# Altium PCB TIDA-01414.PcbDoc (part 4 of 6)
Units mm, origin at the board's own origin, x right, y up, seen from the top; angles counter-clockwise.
Board outline 400 x 135 mm, 4 copper layers (Top Copper, Copper Layer 2, Copper Layer 3, Bottom Copper), stack 1.567 mm thick; 835 components, 519 nets, 2420 pads, 2045 vias.
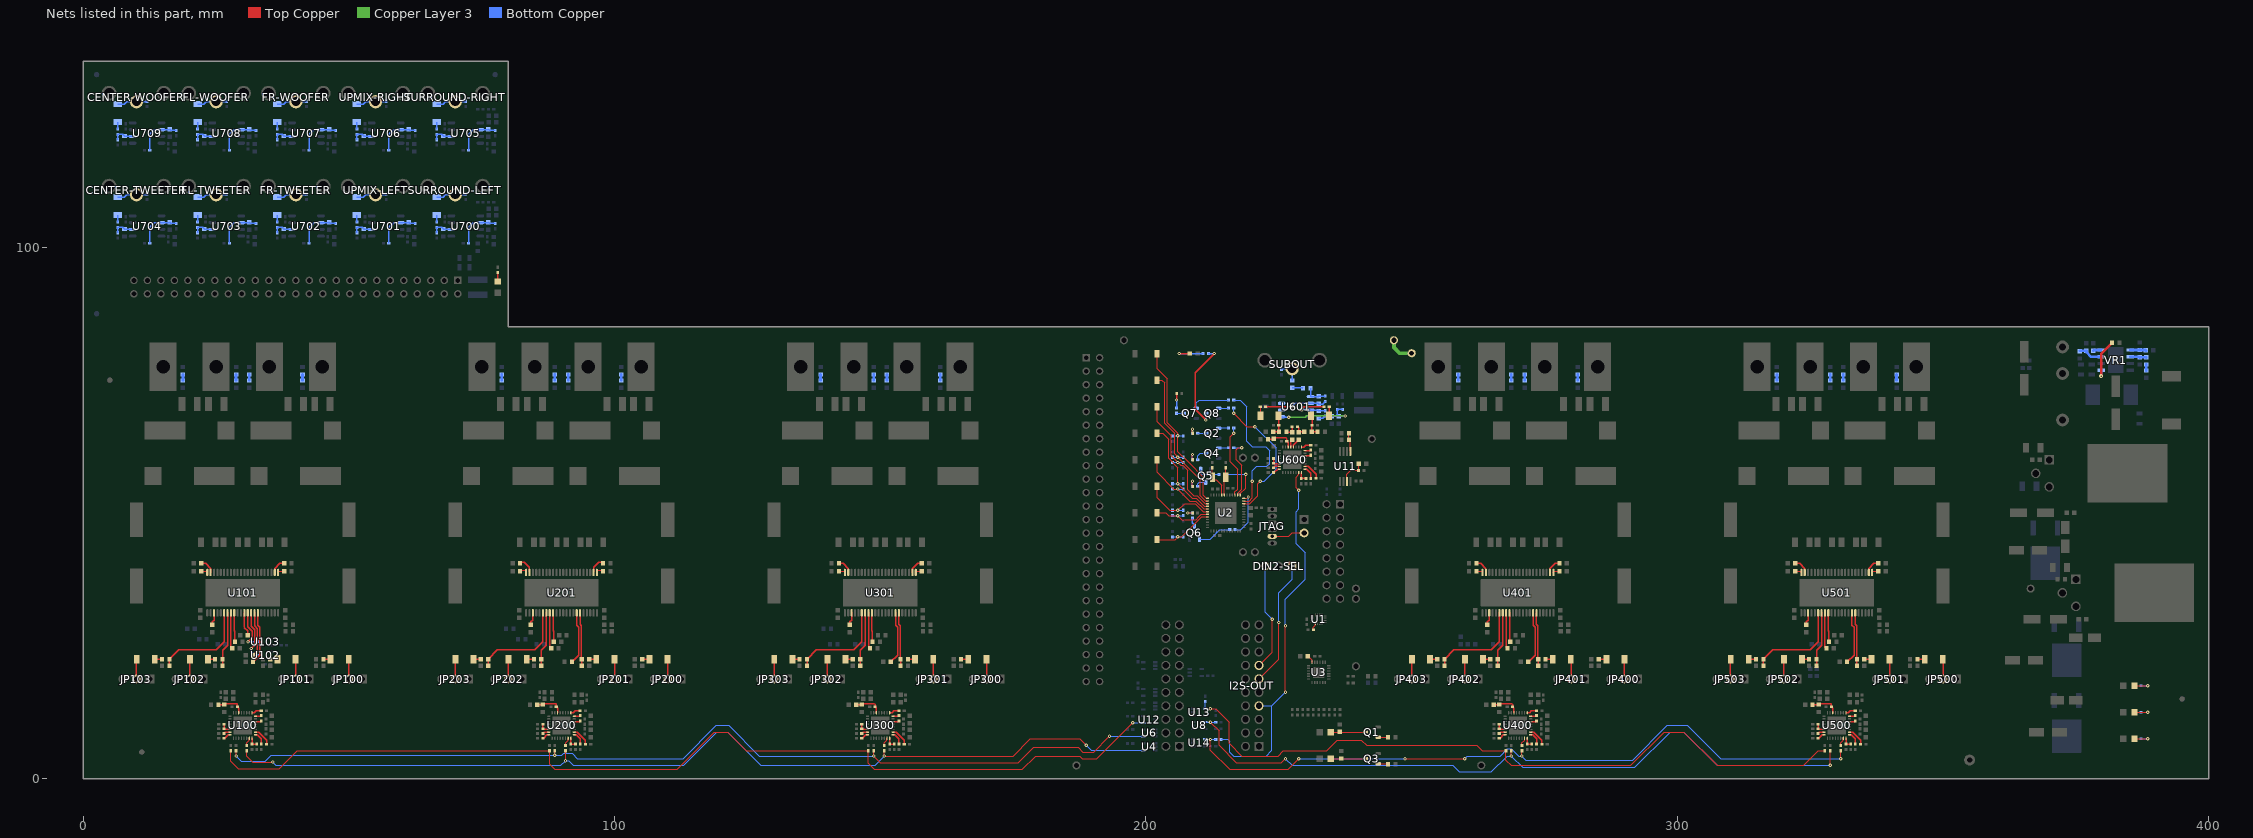
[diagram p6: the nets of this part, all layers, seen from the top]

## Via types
v1: diameter 0.635, hole 0.254, Top Copper to Bottom Copper, tented both sides, 1429 vias
v2: diameter 0.762, hole 0.254, Top Copper to Bottom Copper, tented both sides, 311 vias
v3: diameter 0.5, hole 0.2, Top Copper to Bottom Copper, 150 vias
v4: diameter 0.5, hole 0.2, Top Copper to Bottom Copper, tented both sides, 124 vias
v5: diameter 0.508, hole 0.254, Top Copper to Bottom Copper, tented both sides, 21 vias
v6: diameter 6.5, hole 4.5, Top Copper to Bottom Copper, tented both sides, 9 vias
v7: diameter 0.889, hole 0.254, Top Copper to Bottom Copper, tented both sides, 1 vias

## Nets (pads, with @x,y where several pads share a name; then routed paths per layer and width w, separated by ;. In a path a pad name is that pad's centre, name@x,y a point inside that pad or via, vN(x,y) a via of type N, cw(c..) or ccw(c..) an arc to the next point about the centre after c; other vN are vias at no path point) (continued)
INPUTB2: C225.1 R206.2 U201.17 | length 10.1
  Top Copper w0.25: U201.17@93.493,31.2 93.493,29.008 93.75,28.75 93.75,22.55 R206.2@93.8,22.5 C225.1@93.8,21.25
INPUTB3: C325.1 R306.2 U301.17 | length 10.1
  Top Copper w0.25: U301.17@153.492,31.2 153.492,29.008 153.75,28.75 153.75,22.55 R306.2@153.8,22.5 C325.1@153.8,21.25
INPUTB4: C425.1 R406.2 U401.17 | length 10.1
  Top Copper w0.25: U401.17@273.493,31.2 273.493,29.008 273.75,28.75 273.75,22.55 R406.2@273.8,22.5 C425.1@273.8,21.25
INPUTB5: C525.1 R506.2 U501.17 | length 10.1
  Top Copper w0.25: U501.17@333.493,31.2 333.493,29.008 333.75,28.75 333.75,22.55 R506.2@333.8,22.5 C525.1@333.8,21.25
INPUTC1: C131.1 R108.2 U101.7 | length 10.7
  Top Copper w0.25: C131.1@26.2,21.25 R108.2@26.2,22.75 ; R108.2@26.2,22.5 R108.2@26.2,22.75 ; U101.7@27.143,31.3 U101.7@27.143,31.2 27.143,25.142 26.2,24.2 R108.2@26.2,22.75
INPUTC2: C231.1 R208.2 U201.7 | length 10.7
  Top Copper w0.25: C231.1@86.2,21.25 R208.2@86.2,22.75 ; R208.2@86.2,22.5 R208.2@86.2,22.75 ; U201.7@87.143,31.3 U201.7@87.143,31.2 87.143,25.142 86.2,24.2 R208.2@86.2,22.75
INPUTC3: C331.1 R308.2 U301.7 | length 10.7
  Top Copper w0.25: C331.1@146.2,21.25 R308.2@146.2,22.75 ; R308.2@146.2,22.5 R308.2@146.2,22.75 ; U301.7@147.142,31.3 U301.7@147.142,31.2 147.142,25.142 146.2,24.2 R308.2@146.2,22.75
INPUTC4: C431.1 R408.2 U401.7 | length 10.7
  Top Copper w0.25: C431.1@266.2,21.25 R408.2@266.2,22.75 ; R408.2@266.2,22.5 R408.2@266.2,22.75 ; U401.7@267.143,31.3 U401.7@267.143,31.2 267.143,25.142 266.2,24.2 R408.2@266.2,22.75
INPUTC5: C531.1 R508.2 U501.7 | length 10.7
  Top Copper w0.25: C531.1@326.2,21.25 R508.2@326.2,22.75 ; R508.2@326.2,22.5 R508.2@326.2,22.75 ; U501.7@327.143,31.3 U501.7@327.143,31.2 327.143,25.142 326.2,24.2 R508.2@326.2,22.75
INPUTD1: C137.1 R116.2 U101.6 | length 18.5
  Top Copper w0.25: C137.1@16.2,21.25 16.2,22.45 R116.2@16.25,22.5 ; R116.2@16.2,22.5 17.95,24.25 25,24.25 26.508,25.757 U101.6@26.508,31.2 U101.6@26.508,31.3
INPUTD2: C237.1 R216.2 U201.6 | length 18.4
  Top Copper w0.25: C237.1@76.2,21.25 R216.2@76.2,22.45 ; R216.2@76.2,22.5 77.95,24.25 85,24.25 86.508,25.757 U201.6@86.508,31.2 U201.6@86.508,31.3
INPUTD3: C337.1 R316.2 U301.6 | length 18.4
  Top Copper w0.25: C337.1@136.2,21.25 R316.2@136.2,22.45 ; R316.2@136.2,22.5 137.95,24.25 145,24.25 146.507,25.757 U301.6@146.507,31.2 U301.6@146.507,31.3
INPUTD4: C437.1 R416.2 U401.6 | length 18.4
  Top Copper w0.25: C437.1@256.2,21.25 R416.2@256.2,22.45 ; R416.2@256.2,22.5 257.95,24.25 265,24.25 266.508,25.757 U401.6@266.508,31.2 U401.6@266.508,31.3
INPUTD5: C537.1 R516.2 U501.6 | length 18.4
  Top Copper w0.25: C537.1@316.2,21.25 R516.2@316.2,22.45 ; R516.2@316.2,22.5 317.95,24.25 325,24.25 326.508,25.757 U501.6@326.508,31.2 U501.6@326.508,31.3
LRCK1: R87.1 U100.31 | length 1.6
  Top Copper w0.2: R87.1@30.75,6.25 30.75,6.75 31.25,7.25 U100.31@31.25,7.6
LRCK2: R88.1 U200.31 | length 1.6
  Top Copper w0.2: R88.1@90.75,6.25 90.75,6.75 91.25,7.25 U200.31@91.25,7.6
LRCK3: R89.1 U300.31 | length 1.6
  Top Copper w0.2: R89.1@150.75,6.25 150.75,6.75 151.25,7.25 U300.31@151.25,7.6
LRCK4: R90.1 U400.31 | length 1.6
  Top Copper w0.2: R90.1@270.75,6.25 270.75,6.75 271.25,7.25 U400.31@271.25,7.6
LRCK5: R91.1 U500.31 | length 1.6
  Top Copper w0.2: R91.1@330.75,6.25 330.75,6.75 331.25,7.25 U500.31@331.25,7.6
LRCK6: I2S-OUT.7 R92.1 U600.31 | length 71.1
  Top Copper w0.2: v1(226.25,16.25) v1(226.25,28.75) ; v1(228.75,54.25) 228.25,54.75 228.25,56.75 228.75,57.25 U600.31@228.75,57.6
  Bottom Copper w0.2: R92.1@214.125,7.375 215.375,7.375 215.75,7 215.75,5 216.5,4.25 222.625,4.25 223.69,5.315 223.69,13.69 ; I2S-OUT.7@221.27,13.69 223.69,13.69 ; v1(226.25,16.25) 223.69,13.69 ; v1(226.25,28.75) 226.25,33.75 229.25,36.75 230,37.5 230,42.5 228.625,43.875 228.25,44.25 228.25,50.25 228.75,50.75 v1(228.75,54.25)
NetC1_1: C1.1 VR1.1 | length 8.2
  Top Copper w0.5: v2(379.75,75.75) 379.75,79.95 C1.1@381.8,82
  Bottom Copper w0.5: v2(379.75,75.75) 379.75,76.82 VR1.1@379.775,76.845
NetC2_1: C2.1 R600.2 R604.1 U601.2 | length 11.8
  Top Copper w0.25: R604.1@222.5,70 v2(227.5,70)
  Bottom Copper w0.25: v2(227.5,70) 228.135,70.635 U601.2@230.975,70.635 232.365,70.635 232.5,70.5 233.25,70.5 R600.2@233.75,71
NetC2_2: C2.2 R600.1 R605.1 U601.1 | length 4.4
  Bottom Copper w0.25: R605.1@231,73.5 230.975,73.475 U601.1@230.975,71.905 232.455,71.905 C2.2@232.5,71.95 232.55,72 R600.1@233.75,72
NetC7_1: C7.1 R36.2 VR1.6 | length 3.1
  Bottom Copper w0.5: VR1.6@385.225,79.385 386.865,79.385 C7.1@387,79.25 ; C7.1@387,79.325 388.175,79.325 R36.2@388.25,79.25
NetC25_1: C25.1 MODE3.2 R60.2 U2.18 | length 15.7
  Top Copper w0.2: MODE3.2@202.1,55 202.1,52.9 204.5,50.5 v1(206,50.5) 207.25,51.75 209.25,51.75 210.75,50.25 U2.18@211.6,50.25
  Bottom Copper w0.2: C25.1@205,50.5 v1(206,50.5) R60.2@207,50.5
NetC26_1: C26.1 MODE4.2 R61.2 U2.19 | length 12.4
  Top Copper w0.2: MODE4.2@202.1,50 203.75,50 204.25,49.5 v1(206,49.5) 206.75,48.75 209.424,48.75 209.962,49.288 ; 209.967,49.283 210.434,49.75 U2.19@211.6,49.75
  Bottom Copper w0.2: C26.1@205,49.5 v1(206,49.5) R61.2@207,49.5
NetC27_1: C27.1 R36.1 | length 1.2
  Bottom Copper w0.5: C27.1@388.25,76.825 R36.1@388.25,77.925 R36.1@388.25,78
NetC48_1: C48.1 R39.2 U2.14 VOL-UP.2 | length 29.5
  Top Copper w0.2: VOL-UP.2@202,75 VOL-UP.2@202.1,75 203,75 203.5,74.5 203.5,66.875 205.375,65 205.375,61.125 v1(206,60.5) 210.25,56.25 210.25,53.25 211.25,52.25 U2.14@211.6,52.25
  Bottom Copper w0.2: C48.1@205,60.5 R39.2@207,60.5
NetC49_1: C49.1 R40.2 U2.15 VOL-DN.2 | length 25
  Top Copper w0.2: VOL-DN.2@202.1,70 202.1,67.15 204.75,64.5 204.75,60.75 v1(206,59.5) 206.5,59 206.875,59 207.125,58.75 207.875,58 207.875,54.375 209,53.25 209.625,53.25 211.125,51.75 U2.15@211.6,51.75
  Bottom Copper w0.2: C49.1@205,59.5 v1(206,59.5) R40.2@207,59.5
NetC50_1: C50.1 MODE1.2 R42.2 U2.16 | length 21.2
  Top Copper w0.2: MODE1.2@202.1,65 203.125,65 204.25,63.875 204.25,60.25 206,58.5 v1(206,55.5) 208.75,52.75 209.5,52.75 211,51.25 U2.16@211.6,51.25 U2.16@211.75,51.25
  Bottom Copper w0.2: C50.1@205,55.5 R42.2@207,55.5
NetC51_1: C51.1 MODE2.2 R44.2 U2.17 | length 16.7
  Top Copper w0.2: MODE2.2@202.1,60 202.1,57.65 205.25,54.5 v1(206,54.5) 208.25,52.25 209.375,52.25 210.875,50.75 U2.17@211.6,50.75
  Bottom Copper w0.2: C51.1@205,54.5 v1(206,54.5) R44.2@207,54.5
NetC53_1: C53.1 LOAD.2 R45.2 U2.20 | length 13.3
  Top Copper w0.2: LOAD.2@202.1,45 205.5,45 v1(206,45.5) 206.75,45.5 210.5,49.25 U2.20@211.6,49.25
  Bottom Copper w0.2: C53.1@205,45.5 v1(206,45.5) R45.2@207,45.5
NetC57_1: C57.1 MUTE.2 R38.2 U2.13 | length 33.4
  Top Copper w0.2: MUTE.2@202.1,80 202.1,77.15 204,75.25 204,67 206,65 v1(206,64.5) 206,61.5 208,59.5 210.75,56.75 210.75,53.316 211.316,52.75 U2.13@211.6,52.75
  Bottom Copper w0.2: C57.1@205,64.5 R38.2@207,64.5
NetC58_2: C58.2 U2.8 Y2.2 | length 6.1
  Top Copper w0.2: C58.2@212.5,58.5 Y2.2@212.5,56.75 212.5,56.5 212.75,56.25 213.25,56.25 214.25,55.25 U2.8@214.25,53.4
NetC59_2: C59.2 U2.7 Y2.1 | length 5.2
  Top Copper w0.2: U2.7@214.75,53.4 214.75,56.75 215,57 C59.2@215,58.5
NetC104_1: C104.1 C105.1 R100.2 U100.14 | length 5.4
  Top Copper w0.25: R100.2@25.45,13.875 26.425,13.875 C104.1@26.5,13.95 26.675,14.125 28.875,14.125 29,14 C105.1@29,13.5 29.25,13.25 U100.14@29.25,12.4
NetC110_1: C110.1 JP100.2 | length 3.8
  Top Copper w0.25: JP100.2@50,18.75 C110.1@50,22.5
NetC110_2: C110.2 R102.1 | length 1.3
  Top Copper w0.25: R102.1@45.2,22.5 C110.2@46.55,22.5
NetC116_2: C116.2 R104.2 | length 1.1
  Bottom Copper w0.5: R104.2@41.25,74.95 C116.2@41.25,76.05
NetC119_1: C119.1 JP101.2 | length 3.9
  Top Copper w0.25: C119.1@39.75,22.5 40,22.25 JP101.2@40,18.75
NetC119_2: C119.2 R106.1 | length 1.3
  Top Copper w0.25: R106.1@35.2,22.5 C119.2@36.55,22.5
NetC120_2: C120.2 U101.23 | length 1.4
  Top Copper w0.2: U101.23@36.668,38.7 36.668,38.918 36.75,39 C120.2@37.8,39
NetC122_1: C122.1 U100.6 | length 1.2
  Top Copper w0.25: U100.6@32.4,10.75 33.375,10.75 C122.1@33.5,10.875
NetC122_2: C122.2 U100.8 | length 1.2
  Top Copper w0.25: U100.8@32.4,11.75 33.375,11.75 C122.2@33.5,11.875
NetC123_2: C123.2 U101.24 | length 3
  Top Copper w0.25: U101.24@36.033,38.7 36.033,39.533 37,40.5 C123.2@37.8,40.5
NetC127_2: C127.2 R109.2 | length 1.1
  Bottom Copper w0.5: R109.2@31.25,74.95 C127.2@31.25,76.05
NetC128_1: C128.1 U100.9 | length 1.9
  Top Copper w0.25: U100.9@31.75,12.4 32.2,12.4 32.55,12.75 C128.1@33.5,12.75
NetC129_1: C129.1 JP102.2 | length 3.8
  Top Copper w0.25: JP102.2@20,18.75 C129.1@20,22.5
NetC129_2: C129.2 R108.1 | length 1.3
  Top Copper w0.25: C129.2@23.45,22.5 R108.1@24.75,22.5
NetC130_1: C130.1 U100.2 | length 3.5
  Top Copper w0.25: U100.2@32.4,8.75 32.99,8.75 34.5,7.24 C130.1@34.5,6.5
NetC132_2: C132.2 U101.12 | length 4.4
  Top Copper w0.25: 30.318,28.433 30.95,27.8 C132.2@30.95,27 ; 30.318,28.5 U101.12@30.318,31.2
NetC133_2: C133.2 U101.9 | length 5.6
  Top Copper w0.25: U101.9@28.413,31.3 28.413,27.838 28.5,27.75 28.5,27 C133.2@28.5,25.75
NetC134_1: C134.1 JP103.2 | length 3.8
  Top Copper w0.25: JP103.2@10,18.75 C134.1@10,22.5
NetC134_2: C134.2 R116.1 | length 1.3
  Top Copper w0.25: C134.2@13.5,22.5 R116.1@14.8,22.5
NetC136_2: C136.2 R118.2 | length 1.1
  Bottom Copper w0.5: R118.2@28.75,74.95 C136.2@28.75,76.05
NetC138_2: C138.2 U101.43 | length 3
  Top Copper w0.25: C138.2@22.2,40.5 23,40.5 23.968,39.533 U101.43@23.968,38.7
NetC139_2: C139.2 U101.44 | length 1.4
  Top Copper w0.2: C139.2@22.2,39 23.25,39 23.333,38.917 U101.44@23.333,38.7
NetC141_2: C141.2 R120.2 | length 1.1
  Bottom Copper w0.5: R120.2@18.75,74.95 C141.2@18.75,76.05
NetC142_2: C142.2 U101.3 | length 2.4
  Top Copper w0.25: C142.2@24.25,29 24.25,29.5 24.603,29.853 U101.3@24.603,31.2 U101.3@24.603,31.3
NetC143_1: C143.1 U101.8 | length 6.9
  Top Copper w0.25: U101.8@27.778,31.3 U101.8@27.778,31.2 27.778,24.772 C143.1@28.05,24.5
NetC204_1: C204.1 C205.1 R200.2 U200.14 | length 5.4
  Top Copper w0.25: R200.2@85.45,13.875 86.425,13.875 C204.1@86.5,13.95 86.675,14.125 88.875,14.125 89,14 C205.1@89,13.5 89.25,13.25 U200.14@89.25,12.4
NetC210_1: C210.1 JP200.2 | length 3.8
  Top Copper w0.25: JP200.2@110,18.75 C210.1@110,22.5
NetC210_2: C210.2 R202.1 | length 1.3
  Top Copper w0.25: R202.1@105.2,22.5 C210.2@106.55,22.5
NetC216_2: C216.2 R204.2 | length 1.1
  Bottom Copper w0.5: R204.2@101.25,74.95 C216.2@101.25,76.05
NetC219_1: C219.1 JP201.2 | length 3.9
  Top Copper w0.25: C219.1@99.75,22.5 100,22.25 JP201.2@100,18.75
NetC219_2: C219.2 R206.1 | length 1.3
  Top Copper w0.25: R206.1@95.2,22.5 C219.2@96.55,22.5
NetC220_2: C220.2 U201.23 | length 1.4
  Top Copper w0.2: U201.23@96.668,38.95 96.668,39.168 96.75,39.25 C220.2@97.8,39.25
NetC222_1: C222.1 U200.6 | length 1.2
  Top Copper w0.25: U200.6@92.4,10.75 93.375,10.75 C222.1@93.5,10.875
NetC222_2: C222.2 U200.8 | length 1.2
  Top Copper w0.25: U200.8@92.4,11.75 93.375,11.75 C222.2@93.5,11.875
NetC223_2: C223.2 U201.24 | length 3
  Top Copper w0.25: U201.24@96.033,38.95 96.033,39.783 97,40.75 C223.2@97.8,40.75
NetC227_2: C227.2 R209.2 | length 1.1
  Bottom Copper w0.5: R209.2@91.25,74.95 C227.2@91.25,76.05
NetC228_1: C228.1 U200.9 | length 1.9
  Top Copper w0.25: U200.9@91.75,12.4 92.2,12.4 92.55,12.75 C228.1@93.5,12.75
NetC229_1: C229.1 JP202.2 | length 3.8
  Top Copper w0.25: JP202.2@80,18.75 C229.1@80,22.5
NetC229_2: C229.2 R208.1 | length 1.3
  Top Copper w0.25: C229.2@83.45,22.5 R208.1@84.75,22.5
NetC230_1: C230.1 U200.2 | length 3.5
  Top Copper w0.25: U200.2@92.4,8.75 92.99,8.75 94.5,7.24 C230.1@94.5,6.5
NetC233_2: C233.2 U201.9 | length 5.6
  Top Copper w0.25: U201.9@88.413,31.3 88.413,27.838 88.5,27.75 88.5,27 C233.2@88.5,25.75
NetC234_1: C234.1 JP203.2 | length 3.8
  Top Copper w0.25: JP203.2@70,18.75 C234.1@70,22.5
NetC234_2: C234.2 R216.1 | length 1.3
  Top Copper w0.25: C234.2@73.5,22.5 R216.1@74.8,22.5
NetC236_2: C236.2 R218.2 | length 1.1
  Bottom Copper w0.5: R218.2@88.75,74.95 C236.2@88.75,76.05
NetC238_2: C238.2 U201.43 | length 3
  Top Copper w0.25: C238.2@82.2,40.75 83,40.75 83.968,39.783 U201.43@83.968,38.95
NetC239_2: C239.2 U201.44 | length 1.4
  Top Copper w0.2: C239.2@82.2,39.25 83.25,39.25 83.333,39.167 U201.44@83.333,38.95
NetC241_2: C241.2 R220.2 | length 1.1
  Bottom Copper w0.5: R220.2@78.75,74.95 C241.2@78.75,76.05
NetC242_2: C242.2 U201.3 | length 2.4
  Top Copper w0.25: C242.2@84.25,29 84.25,29.5 84.603,29.853 U201.3@84.603,31.2 U201.3@84.603,31.3
NetC243_1: C243.1 U201.8 | length 6.9
  Top Copper w0.25: U201.8@87.778,31.3 U201.8@87.778,31.2 87.778,24.772 C243.1@88.05,24.5
NetC304_1: C304.1 C305.1 R300.2 U300.14 | length 5.4
  Top Copper w0.25: R300.2@145.45,13.875 146.425,13.875 C304.1@146.5,13.95 146.675,14.125 148.875,14.125 149,14 C305.1@149,13.5 149.25,13.25 U300.14@149.25,12.4
NetC310_1: C310.1 JP300.2 | length 3.8
  Top Copper w0.25: JP300.2@170,18.75 C310.1@170,22.5
NetC310_2: C310.2 R302.1 | length 1.3
  Top Copper w0.25: R302.1@165.2,22.5 C310.2@166.55,22.5
NetC316_2: C316.2 R304.2 | length 1.1
  Bottom Copper w0.5: R304.2@161.25,74.95 C316.2@161.25,76.05
NetC319_1: C319.1 JP301.2 | length 3.9
  Top Copper w0.25: C319.1@159.75,22.5 160,22.25 JP301.2@160,18.75
NetC319_2: C319.2 R306.1 | length 1.3
  Top Copper w0.25: R306.1@155.2,22.5 C319.2@156.55,22.5
NetC320_2: C320.2 U301.23 | length 1.4
  Top Copper w0.2: U301.23@156.667,38.7 156.667,38.918 156.75,39 C320.2@157.8,39
NetC322_1: C322.1 U300.6 | length 1.2
  Top Copper w0.25: U300.6@152.4,10.75 153.375,10.75 C322.1@153.5,10.875
NetC322_2: C322.2 U300.8 | length 1.2
  Top Copper w0.25: U300.8@152.4,11.75 153.375,11.75 C322.2@153.5,11.875
NetC323_2: C323.2 U301.24 | length 3
  Top Copper w0.25: U301.24@156.032,38.7 156.032,39.533 157,40.5 C323.2@157.8,40.5
NetC327_2: C327.2 R309.2 | length 1.1
  Bottom Copper w0.5: R309.2@151.25,74.95 C327.2@151.25,76.05
NetC328_1: C328.1 U300.9 | length 1.9
  Top Copper w0.25: U300.9@151.75,12.4 152.2,12.4 152.55,12.75 C328.1@153.5,12.75
NetC329_1: C329.1 JP302.2 | length 3.8
  Top Copper w0.25: JP302.2@140,18.75 C329.1@140,22.5
NetC329_2: C329.2 R308.1 | length 1.3
  Top Copper w0.25: C329.2@143.45,22.5 R308.1@144.75,22.5
NetC330_1: C330.1 U300.2 | length 3.5
  Top Copper w0.25: U300.2@152.4,8.75 152.99,8.75 154.5,7.24 C330.1@154.5,6.5
NetC333_2: C333.2 U301.9 | length 5.6
  Top Copper w0.25: U301.9@148.412,31.3 148.412,27.838 148.5,27.75 148.5,27 C333.2@148.5,25.75
NetC334_1: C334.1 JP303.2 | length 3.8
  Top Copper w0.25: JP303.2@130,18.75 C334.1@130,22.5
NetC334_2: C334.2 R316.1 | length 1.3
  Top Copper w0.25: C334.2@133.5,22.5 R316.1@134.8,22.5
NetC336_2: C336.2 R318.2 | length 1.1
  Bottom Copper w0.5: R318.2@148.75,74.95 C336.2@148.75,76.05
NetC338_2: C338.2 U301.43 | length 3
  Top Copper w0.25: C338.2@142.2,40.5 143,40.5 143.967,39.533 U301.43@143.967,38.7
NetC339_2: C339.2 U301.44 | length 1.4
  Top Copper w0.2: C339.2@142.2,39 143.25,39 143.332,38.917 U301.44@143.332,38.7
NetC341_2: C341.2 R320.2 | length 1.1
  Bottom Copper w0.5: R320.2@138.75,74.95 C341.2@138.75,76.05
NetC342_2: C342.2 U301.3 | length 2.4
  Top Copper w0.25: C342.2@144.25,29 144.25,29.5 144.602,29.853 U301.3@144.602,31.2 U301.3@144.602,31.3
NetC343_1: C343.1 U301.8 | length 6.9
  Top Copper w0.25: U301.8@147.777,31.3 U301.8@147.777,31.2 147.777,24.772 C343.1@148.05,24.5
NetC404_1: C404.1 C405.1 R400.2 U400.14 | length 5.4
  Top Copper w0.25: R400.2@265.45,13.875 266.425,13.875 C404.1@266.5,13.95 266.675,14.125 268.875,14.125 269,14 C405.1@269,13.5 269.25,13.25 U400.14@269.25,12.4
NetC410_1: C410.1 JP400.2 | length 3.8
  Top Copper w0.25: JP400.2@290,18.75 C410.1@290,22.5
NetC410_2: C410.2 R402.1 | length 1.3
  Top Copper w0.25: R402.1@285.2,22.5 C410.2@286.55,22.5
NetC416_2: C416.2 R404.2 | length 1.1
  Bottom Copper w0.5: R404.2@281.25,74.95 C416.2@281.25,76.05
NetC419_1: C419.1 JP401.2 | length 3.9
  Top Copper w0.25: C419.1@279.75,22.5 280,22.25 JP401.2@280,18.75
NetC419_2: C419.2 R406.1 | length 1.3
  Top Copper w0.25: R406.1@275.2,22.5 C419.2@276.55,22.5
NetC420_2: C420.2 U401.23 | length 1.4
  Top Copper w0.2: U401.23@276.668,38.7 276.668,38.918 276.75,39 C420.2@277.8,39
NetC422_1: C422.1 U400.6 | length 1.2
  Top Copper w0.25: U400.6@272.4,10.75 273.375,10.75 C422.1@273.5,10.875
NetC422_2: C422.2 U400.8 | length 1.2
  Top Copper w0.25: U400.8@272.4,11.75 273.375,11.75 C422.2@273.5,11.875
NetC423_2: C423.2 U401.24 | length 3
  Top Copper w0.25: U401.24@276.033,38.7 276.033,39.533 277,40.5 C423.2@277.8,40.5
NetC427_2: C427.2 R409.2 | length 1.1
  Bottom Copper w0.5: R409.2@271.25,74.95 C427.2@271.25,76.05
NetC428_1: C428.1 U400.9 | length 1.9
  Top Copper w0.25: U400.9@271.75,12.4 272.2,12.4 272.55,12.75 C428.1@273.5,12.75
NetC429_1: C429.1 JP402.2 | length 3.8
  Top Copper w0.25: JP402.2@260,18.75 C429.1@260,22.5
NetC429_2: C429.2 R408.1 | length 1.3
  Top Copper w0.25: C429.2@263.45,22.5 R408.1@264.75,22.5
NetC430_1: C430.1 U400.2 | length 3.5
  Top Copper w0.25: U400.2@272.4,8.75 272.99,8.75 274.5,7.24 C430.1@274.5,6.5
NetC433_2: C433.2 U401.9 | length 5.6
  Top Copper w0.25: U401.9@268.413,31.3 268.413,27.838 268.5,27.75 268.5,27 C433.2@268.5,25.75
NetC434_1: C434.1 JP403.2 | length 3.8
  Top Copper w0.25: JP403.2@250,18.75 C434.1@250,22.5
NetC434_2: C434.2 R416.1 | length 1.3
  Top Copper w0.25: C434.2@253.5,22.5 R416.1@254.8,22.5
NetC436_2: C436.2 R418.2 | length 1.1
  Bottom Copper w0.5: R418.2@268.75,74.95 C436.2@268.75,76.05
NetC438_2: C438.2 U401.43 | length 3
  Top Copper w0.25: C438.2@262.2,40.5 263,40.5 263.968,39.533 U401.43@263.968,38.7
NetC439_2: C439.2 U401.44 | length 1.4
  Top Copper w0.2: C439.2@262.2,39 263.25,39 263.333,38.917 U401.44@263.333,38.7
NetC441_2: C441.2 R420.2 | length 1.1
  Bottom Copper w0.5: R420.2@258.75,74.95 C441.2@258.75,76.05
NetC442_2: C442.2 U401.3 | length 2.4
  Top Copper w0.25: C442.2@264.25,29 264.25,29.5 264.603,29.853 U401.3@264.603,31.2 U401.3@264.603,31.3
NetC443_1: C443.1 U401.8 | length 6.9
  Top Copper w0.25: U401.8@267.778,31.3 U401.8@267.778,31.2 267.778,24.772 C443.1@268.05,24.5
NetC504_1: C504.1 C505.1 R500.2 U500.14 | length 5.4
  Top Copper w0.25: R500.2@325.45,13.875 326.425,13.875 326.5,13.95 326.675,14.125 328.875,14.125 329,14 C505.1@329,13.5 329.25,13.25 U500.14@329.25,12.4
NetC510_1: C510.1 JP500.2 | length 3.8
  Top Copper w0.25: JP500.2@350,18.75 C510.1@350,22.5
NetC510_2: C510.2 R502.1 | length 1.3
  Top Copper w0.25: R502.1@345.2,22.5 C510.2@346.55,22.5
NetC516_2: C516.2 R504.2 | length 1.1
  Bottom Copper w0.5: R504.2@341.25,74.95 C516.2@341.25,76.05
NetC519_1: C519.1 JP501.2 | length 3.9
  Top Copper w0.25: C519.1@339.75,22.5 340,22.25 JP501.2@340,18.75
NetC519_2: C519.2 R506.1 | length 1.3
  Top Copper w0.25: R506.1@335.2,22.5 C519.2@336.55,22.5
NetC520_2: C520.2 U501.23 | length 1.4
  Top Copper w0.2: U501.23@336.668,38.7 336.668,38.918 336.75,39 C520.2@337.8,39
NetC522_1: C522.1 U500.6 | length 1.2
  Top Copper w0.25: U500.6@332.4,10.75 333.375,10.75 C522.1@333.5,10.875
NetC522_2: C522.2 U500.8 | length 1.2
  Top Copper w0.25: U500.8@332.4,11.75 333.375,11.75 C522.2@333.5,11.875
NetC523_2: C523.2 U501.24 | length 3
  Top Copper w0.25: U501.24@336.033,38.7 336.033,39.533 337,40.5 C523.2@337.8,40.5
NetC527_2: C527.2 R509.2 | length 1.1
  Bottom Copper w0.5: R509.2@331.25,74.95 C527.2@331.25,76.05
NetC528_1: C528.1 U500.9 | length 1.9
  Top Copper w0.25: U500.9@331.75,12.4 332.2,12.4 332.55,12.75 C528.1@333.5,12.75
NetC529_1: C529.1 JP502.2 | length 3.8
  Top Copper w0.25: JP502.2@320,18.75 C529.1@320,22.5
NetC529_2: C529.2 R508.1 | length 1.3
  Top Copper w0.25: C529.2@323.45,22.5 R508.1@324.75,22.5
NetC530_1: C530.1 U500.2 | length 3.5
  Top Copper w0.25: U500.2@332.4,8.75 332.99,8.75 334.5,7.24 C530.1@334.5,6.5
NetC533_2: C533.2 U501.9 | length 5.6
  Top Copper w0.25: U501.9@328.413,31.3 328.413,27.838 328.5,27.75 328.5,27 C533.2@328.5,25.75
NetC534_1: C534.1 JP503.2 | length 3.8
  Top Copper w0.25: JP503.2@310,18.75 C534.1@310,22.5
NetC534_2: C534.2 R516.1 | length 1.3
  Top Copper w0.25: C534.2@313.5,22.5 R516.1@314.8,22.5
NetC536_2: C536.2 R518.2 | length 1.1
  Bottom Copper w0.5: R518.2@328.75,74.95 C536.2@328.75,76.05
NetC538_2: C538.2 U501.43 | length 3
  Top Copper w0.25: C538.2@322.2,40.5 323,40.5 323.968,39.533 U501.43@323.968,38.7
NetC539_2: C539.2 U501.44 | length 1.4
  Top Copper w0.2: C539.2@322.2,39 323.25,39 323.333,38.917 U501.44@323.333,38.7
NetC541_2: C541.2 R520.2 | length 1.1
  Bottom Copper w0.5: R520.2@318.75,74.95 C541.2@318.75,76.05
NetC542_2: C542.2 U501.3 | length 2.4
  Top Copper w0.25: C542.2@324.25,29 324.25,29.5 324.603,29.853 U501.3@324.603,31.2 U501.3@324.603,31.3
NetC543_1: C543.1 U501.8 | length 6.9
  Top Copper w0.25: U501.8@327.778,31.3 U501.8@327.778,31.2 327.778,24.772 C543.1@328.05,24.5
NetC600_1: C600.1 C607.1 R1.2 R603.2 | length 4.1
  Top Copper w0.25: C607.1@223.95,65.25 R603.2@225.05,65.25 225,65.3 R1.2@225,66.5 225,68.2 C600.1@224.95,68.25
NetC600_2: C600.2 R604.2 | length 1.8
  Top Copper w0.2: R604.2@221.5,70 221.55,69.95 C600.2@221.55,68.25
NetC601_1: C601.1 C602.1 R601.2 U600.14 | length 5.4
  Top Copper w0.25: R601.2@222.95,63.875 223.925,63.875 C601.1@224,63.95 224.175,64.125 226.375,64.125 226.5,64 C602.1@226.5,63.5 226.75,63.25 U600.14@226.75,62.4
NetC608_1: C608.1 R619.2 SUBOUT.1 | length 4.1
  Bottom Copper w0.25: R619.2@225.5,77 225.65,77.15 SUBOUT.1@227.5,77.15 ; C608.1@227.5,74.95 SUBOUT.1@227.5,77
NetC608_2: C608.2 R605.2 | length 2
  Bottom Copper w0.25: C608.2@227.5,73.55 229.45,73.55 R605.2@229.5,73.5
NetC609_1: C609.1 R602.2 R603.1 | length 2.1
  Top Copper w0.25: R603.1@226.45,65.25 226.5,65.2 R602.2@227.5,65.2 C609.1@227.5,66.25
NetC609_2: C609.2 R607.2 R608.1 | length 2.2
  Top Copper w0.25: C609.2@228.5,66.25 228.75,66 R607.2@228.75,65.2 228.8,65.25 R608.1@229.8,65.25
NetC610_1: C610.1 C612.1 R608.2 R620.2 | length 4.2
  Top Copper w0.25: C610.1@231.05,68.25 231.25,68.05 R620.2@231.25,66.5 231.2,66.45 R608.2@231.2,65.25 C612.1@232.3,65.25
NetC610_2: C610.2 R609.2 | length 1.8
  Top Copper w0.25: C610.2@234.45,68.25 234.5,68.3 R609.2@234.5,70
NetC611_1: C611.1 U600.6 | length 1.2
  Top Copper w0.25: U600.6@229.9,60.75 230.875,60.75 C611.1@231,60.875
NetC611_2: C611.2 U600.8 | length 1.2
  Top Copper w0.25: U600.8@229.9,61.75 230.875,61.75 C611.2@231,61.875
NetC613_1: C613.1 U600.9 | length 1.9
  Top Copper w0.25: U600.9@229.25,62.4 229.7,62.4 230.05,62.75 C613.1@231,62.75
NetC614_2: C614.2 C615.2 C620.1 R606.2 R610.2 R611.1 U601.5 | length 19.7
  Copper Layer 3 w0.25: v1(226.875,68) 230,68 230.25,68.25 v1(237.5,68.25)
  Bottom Copper w0.25: U601.5@225.525,68.095 225.62,68 v1(226.875,68) ; C620.1@232.5,67.8 233.3,67.8 R606.2@233.75,68.25 235,68.25 235.05,68.2 C615.2@236.25,68.2 236.3,68.25 v1(237.5,68.25) ; C615.2@236.25,68.25 236,68.5 R611.1@236,69.5 R610.2@237,69.5
NetC616_1: C616.1 U600.2 | length 3.5
  Top Copper w0.25: U600.2@229.9,58.75 230.49,58.75 232,57.24 C616.1@232,56.5
NetC620_2: C620.2 R606.1 R609.1 U601.3 | length 9.1
  Top Copper w0.25: v2(229.25,69.5) 229.75,70 R609.1@233.5,70
  Bottom Copper w0.25: v2(229.25,69.5) 230.84,69.5 U601.3@230.975,69.365 232.385,69.365 232.5,69.25 R606.1@233.75,69.25
NetC700_1: C700.1 R744.2 SURROUND-LEFT.1 | length 5.7
  Bottom Copper w0.25: C700.1@66.5,109.45 67.7,109.45 68.15,109.9 SURROUND-LEFT.1@70,109.9 71.9,109.9 R744.2@72,110
NetC700_2: C700.2 R705.2 | length 1.3
  Bottom Copper w0.25: R705.2@66.5,104.75 C700.2@66.5,106.05
NetC701_1: C701.1 R745.2 UPMIX-LEFT.1 | length 5.7
  Bottom Copper w0.25: C701.1@51.5,109.45 52.7,109.45 53.15,109.9 UPMIX-LEFT.1@55,109.9 56.9,109.9 R745.2@57,110
NetC701_2: C701.2 R706.2 | length 1.3
  Bottom Copper w0.25: R706.2@51.5,104.75 C701.2@51.5,106.05
NetC702_1: C702.1 FR-TWEETER.1 R746.2 | length 5.7
  Bottom Copper w0.25: C702.1@36.5,109.45 37.7,109.45 38.15,109.9 FR-TWEETER.1@40,109.9 41.9,109.9 R746.2@42,110
NetC702_2: C702.2 R707.2 | length 1.3
  Bottom Copper w0.25: R707.2@36.5,104.75 C702.2@36.5,106.05
NetC703_1: C703.1 FL-TWEETER.1 R747.2 | length 5.7
  Bottom Copper w0.25: C703.1@21.5,109.45 22.7,109.45 23.15,109.9 FL-TWEETER.1@25,109.9 26.9,109.9 R747.2@27,110
NetC703_2: C703.2 R708.2 | length 1.3
  Bottom Copper w0.25: R708.2@21.5,104.75 C703.2@21.5,106.05
NetC704_1: C704.1 CENTER-TWEETER.1 R748.2 | length 5.7
  Bottom Copper w0.25: C704.1@6.5,109.45 7.7,109.45 8.15,109.9 CENTER-TWEETER.1@10,109.9 11.9,109.9 R748.2@12,110
NetC704_2: C704.2 R709.2 | length 1.3
  Bottom Copper w0.25: R709.2@6.5,104.75 C704.2@6.5,106.05
NetC705_1: C705.1 R749.2 SURROUND-RIGHT.1 | length 5.7
  Bottom Copper w0.25: C705.1@66.5,126.95 67.7,126.95 68.15,127.4 SURROUND-RIGHT.1@70,127.4 71.9,127.4 R749.2@72,127.5
NetC705_2: C705.2 R725.2 | length 1.3
  Bottom Copper w0.25: R725.2@66.5,122.25 C705.2@66.5,123.55
NetC706_1: C706.1 R750.2 UPMIX-RIGHT.1 | length 5.7
  Bottom Copper w0.25: C706.1@51.5,126.95 52.7,126.95 53.15,127.4 UPMIX-RIGHT.1@55,127.4 56.9,127.4 R750.2@57,127.5
NetC706_2: C706.2 R726.2 | length 1.3
  Bottom Copper w0.25: R726.2@51.5,122.25 C706.2@51.5,123.55
NetC707_1: C707.1 FR-WOOFER.1 R751.2 | length 5.7
  Bottom Copper w0.25: C707.1@36.5,126.95 37.7,126.95 38.15,127.4 FR-WOOFER.1@40,127.4 41.9,127.4 R751.2@42,127.5
NetC707_2: C707.2 R727.2 | length 1.3
  Bottom Copper w0.25: R727.2@36.5,122.25 C707.2@36.5,123.55
NetC708_1: C708.1 FL-WOOFER.1 R752.2 | length 5.7
  Bottom Copper w0.25: C708.1@21.5,126.95 22.7,126.95 23.15,127.4 FL-WOOFER.1@25,127.4 26.9,127.4 R752.2@27,127.5
NetC708_2: C708.2 R728.2 | length 1.3
  Bottom Copper w0.25: R728.2@21.5,122.25 C708.2@21.5,123.55
NetC709_1: C709.1 CENTER-WOOFER.1 R753.2 | length 5.7
  Bottom Copper w0.25: C709.1@6.5,126.95 7.7,126.95 8.15,127.4 CENTER-WOOFER.1@10,127.4 11.9,127.4 R753.2@12,127.5
NetC709_2: C709.2 R729.2 | length 1.3
  Bottom Copper w0.25: R729.2@6.5,122.25 C709.2@6.5,123.55
NetC727_1: C727.1 R700.2 R705.1 U700.2 | length 3.9
  Bottom Copper w0.25: R700.2@66.5,102.75 R705.1@66.5,103.75 67.45,103.75 C727.1@67.75,103.45 67.835,103.365 U700.2@69.275,103.365
NetC728_1: C728.1 R701.2 R706.1 U701.2 | length 3.9
  Bottom Copper w0.25: R701.2@51.5,102.75 R706.1@51.5,103.75 52.45,103.75 C728.1@52.75,103.45 52.835,103.365 U701.2@54.275,103.365
NetC729_1: C729.1 R702.2 R707.1 U702.2 | length 3.9
  Bottom Copper w0.25: R702.2@36.5,102.75 R707.1@36.5,103.75 37.45,103.75 C729.1@37.75,103.45 37.835,103.365 U702.2@39.275,103.365
NetC730_1: C730.1 R703.2 R708.1 U703.2 | length 3.9
  Bottom Copper w0.25: R703.2@21.5,102.75 R708.1@21.5,103.75 22.45,103.75 C730.1@22.75,103.45 22.835,103.365 U703.2@24.275,103.365
NetC731_1: C731.1 R704.2 R709.1 U704.2 | length 3.9
  Bottom Copper w0.25: R704.2@6.5,102.75 R709.1@6.5,103.75 7.45,103.75 C731.1@7.75,103.45 7.835,103.365 U704.2@9.275,103.365
NetC737_1: C737.1 R710.2 R715.2 U700.6 | length 8.5
  Bottom Copper w0.25: R710.2@72.5,100.75 72.5,103.75 73.385,104.635 U700.6@74.725,104.635 76.185,104.635 C737.1@76.25,104.7 76.45,104.5 R715.2@77.5,104.5
NetC738_1: C738.1 R711.2 R716.2 U701.6 | length 8.5
  Bottom Copper w0.25: R711.2@57.5,100.75 57.5,103.75 58.385,104.635 U701.6@59.725,104.635 61.185,104.635 C738.1@61.25,104.7 61.45,104.5 R716.2@62.5,104.5
NetC739_1: C739.1 R712.2 R717.2 U702.6 | length 8.5
  Bottom Copper w0.25: R712.2@42.5,100.75 42.5,103.75 43.385,104.635 U702.6@44.725,104.635 46.185,104.635 C739.1@46.25,104.7 46.45,104.5 R717.2@47.5,104.5
NetC740_1: C740.1 R713.2 R718.2 U703.6 | length 8.5
  Bottom Copper w0.25: R713.2@27.5,100.75 27.5,103.75 28.385,104.635 U703.6@29.725,104.635 31.185,104.635 C740.1@31.25,104.7 31.45,104.5 R718.2@32.5,104.5
NetC741_1: C741.1 R714.2 R719.2 U704.6 | length 8.5
  Bottom Copper w0.25: R714.2@12.5,100.75 12.5,103.75 13.385,104.635 U704.6@14.725,104.635 16.185,104.635 C741.1@16.25,104.7 16.45,104.5 R719.2@17.5,104.5
NetC742_1: C742.1 R720.2 R725.1 U705.2 | length 3.9
  Bottom Copper w0.25: R720.2@66.5,120.25 R725.1@66.5,121.25 67.45,121.25 C742.1@67.75,120.95 67.835,120.865 U705.2@69.275,120.865
NetC743_1: C743.1 R721.2 R726.1 U706.2 | length 3.9
  Bottom Copper w0.25: R721.2@51.5,120.25 R726.1@51.5,121.25 52.45,121.25 C743.1@52.75,120.95 52.835,120.865 U706.2@54.275,120.865
NetC744_1: C744.1 R722.2 R727.1 U707.2 | length 3.9
  Bottom Copper w0.25: R722.2@36.5,120.25 R727.1@36.5,121.25 37.45,121.25 C744.1@37.75,120.95 37.835,120.865 U707.2@39.275,120.865
NetC745_1: C745.1 R723.2 R728.1 U708.2 | length 3.9
  Bottom Copper w0.25: R723.2@21.5,120.25 R728.1@21.5,121.25 22.45,121.25 C745.1@22.75,120.95 22.835,120.865 U708.2@24.275,120.865
NetC746_1: C746.1 R724.2 R729.1 U709.2 | length 3.9
  Bottom Copper w0.25: R724.2@6.5,120.25 R729.1@6.5,121.25 7.45,121.25 C746.1@7.75,120.95 7.835,120.865 U709.2@9.275,120.865
NetC752_1: C752.1 R730.2 R735.2 U705.6 | length 8.5
  Bottom Copper w0.25: R730.2@72.5,118.25 72.5,121.25 73.385,122.135 U705.6@74.725,122.135 76.185,122.135 C752.1@76.25,122.2 76.45,122 R735.2@77.5,122
NetC753_1: C753.1 R731.2 R736.2 U706.6 | length 8.5
  Bottom Copper w0.25: R731.2@57.5,118.25 57.5,121.25 58.385,122.135 U706.6@59.725,122.135 61.185,122.135 C753.1@61.25,122.2 61.45,122 R736.2@62.5,122
NetC754_1: C754.1 R732.2 R737.2 U707.6 | length 8.5
  Bottom Copper w0.25: R732.2@42.5,118.25 42.5,121.25 43.385,122.135 U707.6@44.725,122.135 46.185,122.135 C754.1@46.25,122.2 46.45,122 R737.2@47.5,122
NetC755_1: C755.1 R733.2 R738.2 U708.6 | length 8.5
  Bottom Copper w0.25: R733.2@27.5,118.25 27.5,121.25 28.385,122.135 U708.6@29.725,122.135 31.185,122.135 C755.1@31.25,122.2 31.45,122 R738.2@32.5,122
NetC756_1: C756.1 R734.2 R739.2 U709.6 | length 8.5
  Bottom Copper w0.25: R734.2@12.5,118.25 12.5,121.25 13.385,122.135 U709.6@14.725,122.135 16.185,122.135 C756.1@16.25,122.2 16.45,122 R739.2@17.5,122
NetD1_2: D1.2 R62.1 | length 2
  Top Copper w0.2: v1(208.75,61) 208.75,60.05 D1.2@208.8,60
  Bottom Copper w0.2: R62.1@208.75,60 v1(208.75,61)
NetD2_2: D2.2 R65.1 | length 2
  Top Copper w0.2: v1(208.75,56) 208.75,55.05 D2.2@208.8,55
  Bottom Copper w0.2: R65.1@208.75,55 v1(208.75,56)
NetD3_2: D3.2 R68.1 | length 1.8
  Top Copper w0.2: v1(207.875,50) D3.2@208.8,50
  Bottom Copper w0.2: v1(207.875,50) R68.1@208.75,50
NetD4_2: D4.2 R70.1 | length 2.8
  Top Copper w0.25: v1(205.75,71.25) 205.75,72.45 D4.2@205.8,72.5
  Bottom Copper w0.25: R70.1@205.75,69.75 v1(205.75,71.25)
NetD5_2: D5.2 R46.1 | length 1.4
  Top Copper w0.2: D5.2@208.75,65.125 v1(208.75,65.75)
  Bottom Copper w0.2: R46.1@208.75,65 v1(208.75,65.75)
NetD6_2: D6.2 R72.1 | length 6.4
  Top Copper w0.25: v1(206.25,80) D6.2@208.125,80
  Bottom Copper w0.25: v1(206.25,80) R72.1@210.75,80
NetD13_2: D13.2 R51.1 | length 3.7
  Top Copper w0.2: D13.2@386.05,17.5 v1(388.5,17.5)
  Bottom Copper w0.2: R51.1@387.25,17.5 v1(388.5,17.5)
NetD14_2: D14.2 R52.1 | length 3.7
  Top Copper w0.2: D14.2@386.05,12.5 v1(388.5,12.5)
  Bottom Copper w0.2: R52.1@387.25,12.5 v1(388.5,12.5)
NetD15_2: D15.2 R53.1 | length 3.7
  Top Copper w0.2: D15.2@386.05,7.5 v1(388.5,7.5)
  Bottom Copper w0.2: R53.1@387.25,7.5 v1(388.5,7.5)
NetD700_2: D700.2 R754.1 | length 1.7
  Top Copper w0.25: D700.2@78,93.55 R754.1@78,95.25
NetDIN2-SEL_1: DIN2-SEL.1 I2S-OUT.11 | length 23.8
  Top Copper w0.2: I2S-OUT.11@221.27,18.77 225,22.5 v1(225,29.375)
  Bottom Copper w0.2: v1(225,29.375) 225,35 227.54,37.54 DIN2-SEL.1@227.54,40
NetDIN2-SEL_3: DIN2-SEL.3 I2S-OUT.13 | length 20.3
  Top Copper w0.2: I2S-OUT.13@221.27,21.31 223.75,23.79 v1(223.75,30)
  Bottom Copper w0.2: DIN2-SEL.3@222.46,40 222.46,31.29 v1(223.75,30)
NetFAULT_1: FAULT.1 Q3.3 R26.2 | length 6.9
  Top Copper w0.2: FAULT.1@234.8,3.75 R26.2@236.75,3.75 ; R26.2@237,4 R26.2@236.75,3.75 ; Q3.3@241.3,3.75 R26.2@236.75,3.75
NetJ4_2: J4.2 J5.1 | length 5.2
  Copper Layer 3 w0.75: J5.1@246.65,82.5 246.65,81.1 247.693,80.057 J4.2@250.007,80.057
NetJ11_2: J11.2 JTAG.5 | length 6.3
  Top Copper w0.2: JTAG.5@223.75,45.595 226.845,45.595 227.5,46.25 J11.2@229.75,46.25
NetOTW_1: OTW.1 Q1.3 R18.2 | length 6.5
  Top Copper w0.2: OTW.1@234.8,8.75 Q1.3@241.3,8.75
NetQ1_1: Q1.1 R20.1 | length 1.8
  Top Copper w0.2: Q1.1@243.7,7.8 245.45,7.8 R20.1@245.5,7.75
NetQ2_1: Q2.1 R50.1 | length 1.8
  Bottom Copper w0.2: Q2.1@213.75,66 R50.1@215.5,66
NetQ2_3: Q2.3 R46.2 | length 1.7
  Bottom Copper w0.2: R46.2@209.75,65 Q2.3@211.3,65 Q2.3@211.5,65
NetQ3_1: Q3.1 R28.1 | length 1.8
  Top Copper w0.2: Q3.1@243.7,2.8 245.45,2.8 R28.1@245.5,2.75
NetQ4_1: Q4.1 R63.1 | length 2
  Bottom Copper w0.2: Q4.1@213.5,62.25 R63.1@215.5,62.25
NetQ4_3: Q4.3 R62.2 | length 2.7
  Bottom Copper w0.2: R62.2@209.75,60 209.75,60.75 210.25,61.25 Q4.3@211.3,61.25 Q4.3@211.5,61.25
NetQ5_1: Q5.1 R67.1 | length 4.3
  Bottom Copper w0.2: Q5.1@210.3,58.2 210.3,57.45 210.5,57.25 R67.1@213.75,57.25
NetQ5_3: Q5.3 R65.2 | length 2.1
  Bottom Copper w0.2: R65.2@209.75,55 209.75,55.5 210.05,55.8 Q5.3@211.25,55.8
NetQ6_1: Q6.1 R69.1 | length 6.8
  Bottom Copper w0.2: Q6.1@210.075,45.05 212.05,45.05 213.5,46.5 ; 213.25,46.25 213.875,46.875 R69.1@215.75,46.875
NetQ6_3: Q6.3 R68.2 | length 1.7
  Bottom Copper w0.25: R68.2@208.75,49 208.75,48.125 209.125,47.75 Q6.3@209.125,47.45
NetQ7_1: Q7.1 R71.1 | length 7.3
  Bottom Copper w0.2: Q7.1@209.45,69.7 209.45,70.7 210,71.25 R71.1@215.5,71.25
NetQ7_3: Q7.3 R70.2 | length 1.3
  Bottom Copper w0.2: R70.2@205.75,68.75 Q7.3@207,68.75
NetQ8_1: Q8.1 R73.1 | length 2
  Bottom Copper w0.2: Q8.1@213.5,69.75 R73.1@215.5,69.75
NetQ8_3: Q8.3 R72.2 | length 17.2
  Top Copper w0.25: v1(211.25,67.5) 209.25,69.5 209.25,76.375 v1(212.875,80)
  Bottom Copper w0.25: v1(211.25,67.5) Q8.3@211.25,68.75 ; R72.2@211.75,80 v1(212.875,80)
NetR2_1: R2.1 R64.1 U11.7 | length 5.2
  Top Copper w0.2: U11.7@237.825,55.9 237.825,57.325 238.5,58 R64.1@240,58 R2.1@240,59.2 ; R2.1@240,59.25 R2.1@240,59.2 ; R2.1@240.05,59.25 R2.1@240,59.2
NetR17_2: R17.2 U101.15 | length 8.6
  Top Copper w0.25: R17.2@31.95,23.25 32.75,24.05 32.75,28.25 32.223,28.778 U101.15@32.223,31.3
NetR34_1: R34.1 R37.2 VR1.5 | length 3.1
  Bottom Copper w0.5: VR1.5@385.225,80.655 386.905,80.655 R34.1@387,80.75 ; R34.1@387,80.675 388.075,80.675 R37.2@388.25,80.5
NetR35_1: R35.1 R47.2 VR1.3 | length 4.7
  Bottom Copper w0.5: R35.1@375.75,80.5 375.8,80.55 R47.2@377,80.55 ; R47.2@377,80.5 377,80.25 377.865,79.385 VR1.3@379.775,79.385
NetR48_2: R48.2 VR1.4 | length 1.6
  Bottom Copper w0.5: R48.2@378.25,80.5 378.405,80.655 VR1.4@379.775,80.655
NetR50_2: R50.2 U2.3 | length 13.6
  Top Copper w0.2: v1(216.5,65) 215.875,64.375 215.875,59.625 217.25,58.25 217.25,54.5 216.75,54 U2.3@216.75,53.4
  Bottom Copper w0.2: v1(216.5,65) R50.2@216.5,66
NetR59_2: R59.2 U1.1 | length 1.4
  Top Copper w0.2: R59.2@231.5,28 231.5,28.5 231.9,28.9 U1.1@231.9,29.25
NetR63_2: R63.2 U2.2 | length 11.9
  Top Copper w0.2: U2.2@217.25,53.4 217.25,53.75 218,54.5 218,59 217,60 217,61.875 217.375,62.25 v1(218,62.25)
  Bottom Copper w0.2: R63.2@216.5,62.25 v1(218,62.25)
NetR66_1: R66.1 U3.24 | length 1.4
  Top Copper w0.2: R66.1@230.5,23 231.25,22.25 U3.24@231.25,21.9
NetR67_2: R67.2 U2.1 | length 8.3
  Top Copper w0.2: U2.1@217.75,53.4 217.75,53.684 218.75,54.684 v1(218.75,57.25)
  Bottom Copper w0.2: R67.2@214.75,57.25 v1(218.75,57.25)
NetR69_2: R69.2 U2.48 | length 8.8
  Top Copper w0.2: U2.48@218.4,52.75 219,52.75 v5(219.25,53)
  Bottom Copper w0.2: R69.2@216.75,46.875 217.875,46.875 218.75,47.75 219.25,48.25 v5(219.25,53)
NetR71_2: R71.2 U2.47 | length 27.7
  Top Copper w0.2: U2.47@218.4,52.25 219.434,52.25 220,52.816 v1(220,56)
  Bottom Copper w0.2: R71.2@216.5,71.25 217.75,71.25 219,70 219,63.5 220,62.5 222.5,62.5 223.25,61.75 223.25,59.25 222.75,58.75 220.85,58.75 220,57.9 v1(220,56)
NetR73_2: R73.2 U2.46 | length 25.8
  Top Copper w0.2: v1(216.5,68.75) 219,66.25 v1(220.5,66.25) ; U2.46@218.4,51.75 219.5,51.75 221,53.25 221,55.5 v1(221.5,56)
  Bottom Copper w0.2: v1(216.5,68.75) R73.2@216.5,69.75 ; v1(220.5,66.25) 224.5,62.25 224.5,58.25 222.25,56 v1(221.5,56)
NetR75_2: R75.2 R76.2 R77.2 U6.4 | length 183.4
  Top Copper w0.2: v1(28.75,4.25) R75.2@28.75,5.25 ; v1(88.75,4.375) R76.2@88.75,5.25 ; R77.2@148.75,5.25 v1(148.75,4.25) 150,3 176,3 178.875,5.875 187.25,5.875 188.125,5 190.125,5 v1(193.125,8)
  Bottom Copper w0.2: v1(28.75,4.25) 29.75,3.25 34.25,3.25 35.375,4.375 v1(88.75,4.375) 90,4.375 90.375,4.75 92,4.75 93,3.75 112.875,3.75 119.125,10 121.5,10 127.25,4.25 v1(148.75,4.25) ; v1(193.125,8) 199.475,8 U6.4@199.5,7.975
NetR78_2: R78.2 R79.2 R80.2 U8.4 | length 136
  Top Copper w0.2: v1(212.125,10.625) 213.75,9 213.75,6.25 217,3 225.5,3 v1(226.25,3.75) ; v1(268.75,4.25) R78.2@268.75,5.25 ; v1(328.75,2.5) R79.2@328.75,5.25
  Bottom Copper w0.2: U8.4@211.125,10.65 213.1,10.65 R80.2@213.125,10.625 ; v1(226.25,3.75) 227.5,2.5 257.75,2.5 259,1.25 265,1.25 268,4.25 v1(268.75,4.25) 270.875,2.125 292,2.125 298.625,8.75 301.25,8.75 307.5,2.5 v1(328.75,2.5)
NetR81_2: R81.2 R82.2 R83.2 U12.4 | length 189.9
  Top Copper w0.2: R81.2@27.75,5.25 27.75,3.25 29.125,1.875 36.875,1.875 40.25,5.25 R82.2@87.75,5.25 87.75,2.75 88.75,1.75 111.75,1.75 118.75,8.75 121.25,8.75 124.75,5.25 R83.2@147.75,5.25 147.75,2.875 148.875,1.75 176.75,1.75 179.25,4.25 187.5,4.25 188,3.75 190.75,3.75 v1(197.5,10.5)
  Bottom Copper w0.2: v1(197.5,10.5) 199.475,10.5 U12.4@199.5,10.475
NetR84_2: R84.2 R85.2 R86.2 U13.4 | length 134.6
  Top Copper w0.2: v1(212.125,13.125) 213.125,13.125 215.625,10.625 215.625,6.625 218,4.25 224.875,4.25 225.875,5.25 234,5.25 236,7.25 240.5,7.25 241.5,6.25 262.25,6.25 263.25,5.25 R84.2@267.75,5.25 267.75,3.5 268.75,2.5 291.25,2.5 297.5,8.75 301.25,8.75 307.5,2.5 323.75,2.5 326.5,5.25 R85.2@327.75,5.25
  Bottom Copper w0.2: R86.2@211.25,14.5 211.125,14.375 U13.4@211.125,13.15 211.15,13.125 v1(212.125,13.125)
NetR87_2: R87.2 R88.2 R89.2 U4.4 | length 182.2
  Top Copper w0.2: R87.2@30.75,5.25 30.75,4.25 31.875,3.125 v1(35.625,3.125) ; v1(90.75,3.375) R88.2@90.75,5.25 ; R89.2@150.75,5.25 v1(150.75,4.25) 175,4.25 178.25,7.5 187.5,7.5 v1(188.75,6.25)
  Bottom Copper w0.2: v1(35.625,3.125) 36.25,2.5 89.875,2.5 v1(90.75,3.375) 91.375,3.375 92.25,2.5 113,2.5 119.25,8.75 121.25,8.75 127.5,2.5 149,2.5 v1(150.75,4.25) ; v1(188.75,6.25) 189.65,5.35 U4.4@199.5,5.35
NetR90_2: R90.2 R91.2 R92.2 U14.4 | length 134.4
  Top Copper w0.2: v1(212.125,7.375) 212.125,5.375 215.75,1.75 226.75,1.75 v1(228.75,3.75) ; v1(248.75,3.75) v1(260,3.75) ; v1(270.75,4.25) R90.2@270.75,5.25 ; v1(330.75,3.75) R91.2@330.75,5.25
  Bottom Copper w0.2: U14.4@211.125,7.4 213.1,7.4 R92.2@213.125,7.375 ; v1(228.75,3.75) v1(248.75,3.75) ; v1(260,3.75) 260.5,4.25 266.625,4.25 268,5.625 268.75,5.625 270.125,4.25 v1(270.75,4.25) 271.5,3.5 291.625,3.5 298.125,10 301.875,10 308.125,3.75 v1(330.75,3.75)
NetR93_1: R93.1 R94.1 U11.1 | length 3.5
  Top Copper w0.2: R94.1@238.2,63.75 238.2,64.95 R93.1@238.25,65 ; R94.1@238.25,63.75 238.475,63.525 U11.1@238.475,61.6
NetR110_1: R110.1 R113.2 U100.32 | length 2
  Top Copper w0.25: U100.32@31.75,7.6 R113.2@31.75,6.5 R110.1@32.625,6.5
NetR111_1: R111.1 R114.2 U100.22 | length 2
  Top Copper w0.25: R111.1@26.5,10.25 R114.2@26.5,9.375 26.625,9.25 U100.22@27.6,9.25
NetR112_2: R112.2 U100.1 | length 2.4
  Top Copper w0.25: U100.1@32.4,8.25 32.75,8.25 33.5,7.5 R112.2@33.5,6.5
NetR115_1: R115.1 U100.23 | length 1.2
  Top Copper w0.25: R115.1@26.5,8.5 26.75,8.75 U100.23@27.6,8.75
NetR117_1: R117.1 U100.24 | length 1.4
  Top Copper w0.25: R117.1@26.5,7.625 26.635,7.625 27.26,8.25 U100.24@27.6,8.25
NetR119_2: R119.2 U101.16 | length 10
  Top Copper w0.25: R119.2@31.95,22 32,22 33.25,23.25 33.25,28.5 32.858,28.892 U101.16@32.858,31.3
NetR210_1: R210.1 R213.2 U200.32 | length 2
  Top Copper w0.25: U200.32@91.75,7.6 R213.2@91.75,6.5 R210.1@92.625,6.5
NetR211_1: R211.1 R214.2 U200.22 | length 2
  Top Copper w0.25: R211.1@86.5,10.25 R214.2@86.5,9.375 86.625,9.25 U200.22@87.6,9.25
NetR212_2: R212.2 U200.1 | length 2.4
  Top Copper w0.25: U200.1@92.4,8.25 92.75,8.25 93.5,7.5 R212.2@93.5,6.5
NetR215_1: R215.1 U200.23 | length 1.2
  Top Copper w0.25: R215.1@86.5,8.5 86.75,8.75 U200.23@87.6,8.75
NetR217_1: R217.1 U200.24 | length 1.4
  Top Copper w0.25: R217.1@86.5,7.625 86.635,7.625 87.26,8.25 U200.24@87.6,8.25
NetR219_2: R219.2 U201.16 | length 10
  Top Copper w0.25: R219.2@91.95,22 92,22 93.25,23.25 93.25,28.5 92.858,28.892 U201.16@92.858,31.3
NetR310_1: R310.1 R313.2 U300.32 | length 2
  Top Copper w0.25: U300.32@151.75,7.6 R313.2@151.75,6.5 R310.1@152.625,6.5
NetR311_1: R311.1 R314.2 U300.22 | length 2
  Top Copper w0.25: R311.1@146.5,10.25 R314.2@146.5,9.375 146.625,9.25 U300.22@147.6,9.25
NetR312_2: R312.2 U300.1 | length 2.4
  Top Copper w0.25: U300.1@152.4,8.25 152.75,8.25 153.5,7.5 R312.2@153.5,6.5
NetR315_1: R315.1 U300.23 | length 1.2
  Top Copper w0.25: R315.1@146.5,8.5 146.75,8.75 U300.23@147.6,8.75
NetR317_1: R317.1 U300.24 | length 1.4
  Top Copper w0.25: R317.1@146.5,7.625 146.635,7.625 147.26,8.25 U300.24@147.6,8.25
NetR319_2: R319.2 U301.16 | length 10
  Top Copper w0.25: R319.2@151.95,22 152,22 153.25,23.25 153.25,28.5 152.857,28.892 U301.16@152.857,31.3
NetR410_1: R410.1 R413.2 U400.32 | length 2
  Top Copper w0.25: U400.32@271.75,7.6 R413.2@271.75,6.5 R410.1@272.625,6.5
NetR411_1: R411.1 R414.2 U400.22 | length 2
  Top Copper w0.25: R411.1@266.5,10.25 R414.2@266.5,9.375 266.625,9.25 U400.22@267.6,9.25
NetR412_2: R412.2 U400.1 | length 2.4
  Top Copper w0.25: U400.1@272.4,8.25 272.75,8.25 273.5,7.5 R412.2@273.5,6.5
NetR415_1: R415.1 U400.23 | length 1.2
  Top Copper w0.25: R415.1@266.5,8.5 266.75,8.75 U400.23@267.6,8.75
NetR417_1: R417.1 U400.24 | length 1.4
  Top Copper w0.25: R417.1@266.5,7.625 266.635,7.625 267.26,8.25 U400.24@267.6,8.25
NetR419_2: R419.2 U401.16 | length 10
  Top Copper w0.25: R419.2@271.95,22 272,22 273.25,23.25 273.25,28.5 272.858,28.892 U401.16@272.858,31.3
NetR510_1: R510.1 R513.2 U500.32 | length 2
  Top Copper w0.25: U500.32@331.75,7.6 R513.2@331.75,6.5 R510.1@332.625,6.5
NetR511_1: R511.1 R514.2 U500.22 | length 2
  Top Copper w0.25: R511.1@326.5,10.25 R514.2@326.5,9.375 326.625,9.25 U500.22@327.6,9.25
NetR512_2: R512.2 U500.1 | length 2.4
  Top Copper w0.25: U500.1@332.4,8.25 332.75,8.25 333.5,7.5 R512.2@333.5,6.5
NetR515_1: R515.1 U500.23 | length 1.2
  Top Copper w0.25: R515.1@326.5,8.5 326.75,8.75 U500.23@327.6,8.75
NetR517_1: R517.1 U500.24 | length 1.4
  Top Copper w0.25: R517.1@326.5,7.625 326.635,7.625 327.26,8.25 U500.24@327.6,8.25
NetR519_2: R519.2 U501.16 | length 10
  Top Copper w0.25: R519.2@331.95,22 332,22 333.25,23.25 333.25,28.5 332.858,28.892 U501.16@332.858,31.3
NetR602_1: R602.1 U600.13 | length 1.5
  Top Copper w0.25: U600.13@227.25,62.4 227.25,63.55 R602.1@227.5,63.8
NetR607_1: R607.1 U600.12 | length 1.8
  Top Copper w0.25: U600.12@227.75,62.4 227.75,62.75 228.75,63.75 R607.1@228.75,63.8
NetR612_1: R612.1 R615.2 U600.32 | length 2
  Top Copper w0.25: U600.32@229.25,57.6 R615.2@229.25,56.5 R612.1@230.125,56.5
NetR613_1: R613.1 R616.2 U600.22 | length 2
  Top Copper w0.25: R613.1@224,60.25 R616.2@224,59.375 224.125,59.25 U600.22@225.1,59.25
NetR614_2: R614.2 U600.1 | length 2.4
  Top Copper w0.25: U600.1@229.9,58.25 230.25,58.25 231,57.5 R614.2@231,56.5
NetR617_1: R617.1 U600.23 | length 1.2
  Top Copper w0.25: R617.1@224,58.5 224.25,58.75 U600.23@225.1,58.75
NetR618_1: R618.1 U600.24 | length 1.4
  Top Copper w0.25: R618.1@224,57.625 224.135,57.625 224.76,58.25 U600.24@225.1,58.25
NetU101_13: U101.13 U103.2 | length 8.3
  Top Copper w0.25: U101.13@30.953,31.3 30.953,28.548 31.75,27.75 31.75,26.5 v1(31,25.75)
  Bottom Copper w0.25: v1(31,25.75) U103.2@33.125,25.75
NetU101_14: U101.14 U102.2 | length 9.7
  Top Copper w0.25: U101.14@31.588,31.3 31.588,28.663 32.25,28 32.25,25.125 v1(31.625,24.5)
  Bottom Copper w0.25: v1(31.625,24.5) 31.625,23.875 32.25,23.25 U102.2@33.125,23.25
NetU601_6: U601.6 U601.7 | length 1.3
  Bottom Copper w0.25: U601.7@225.5,70.625 225.525,70.6 U601.6@225.525,69.365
